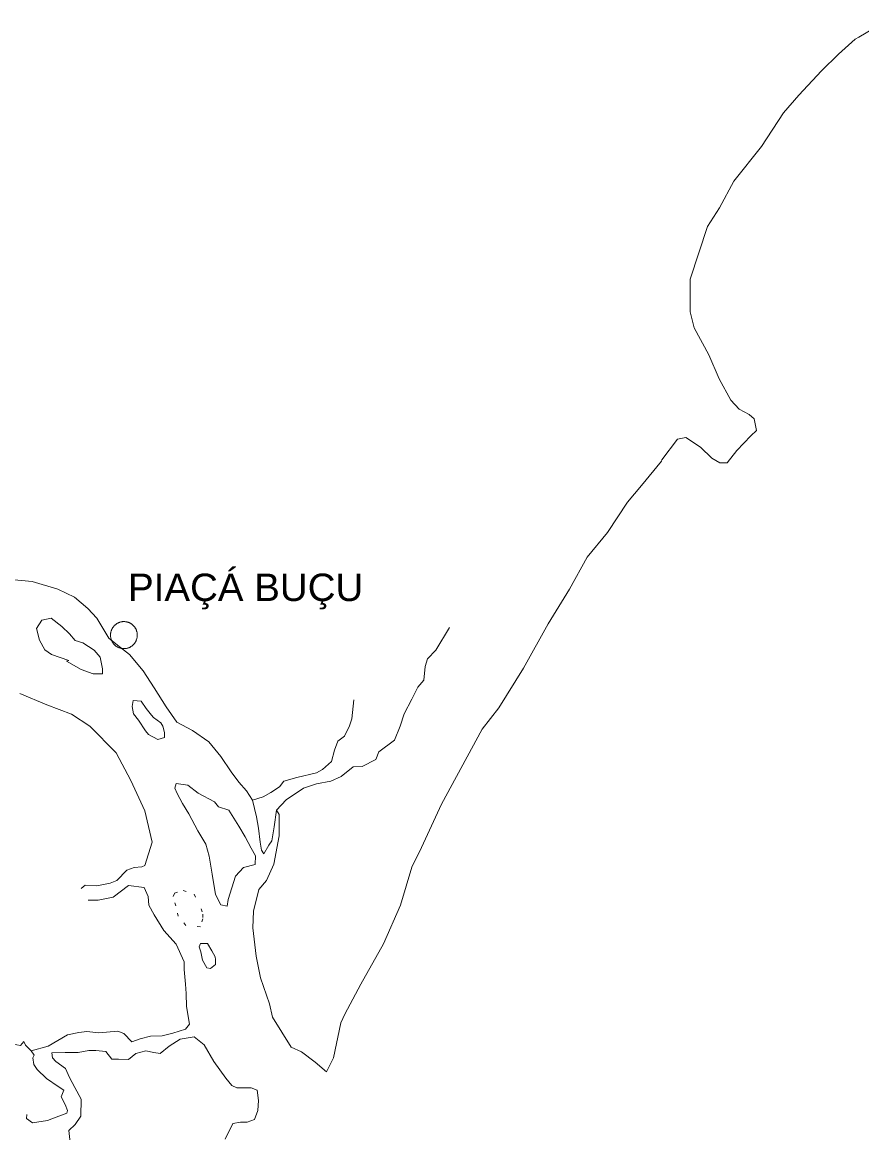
# Model space of a CAD drawing. Extents: x 47169 to 972804, y 7447977 to 9608469.
# Drawn here: x 778748 to 799346, y 8836489 to 8863725 of the extents above; entities that cross this region are included whole.
import ezdxf

# ---------------------------------------------------------------- set-up
doc = ezdxf.new("R2010")
doc.units = 0
doc.header["$LTSCALE"] = 270
doc.linetypes.add('DOTTED', pattern=[1.5, 0.3, -1.2])
doc.layers.add('1', color=7, linetype='Continuous', lineweight=13)
doc.layers.add('3', color=7, linetype='Continuous')

msp = doc.modelspace()

# ---------------------------------------------------------------- linework, layer by layer
at = {"layer": '1'}
for points in [[(799271.3, 8863361), (799891.1, 8863725.4)], [(795667.6, 8853035.2), (795864, 8852922.8), (796039.3, 8852921.3), (796282.9, 8853218.1), (796625.8, 8853580.5), (796758.4, 8853712.2), (796706.1, 8854000.4), (796586.4, 8854101.1), (796335.4, 8854236.1), (796129.1, 8854459.2), (795848.5, 8854981.8), (795590.5, 8855570.7), (795234.3, 8856226.8), (795139, 8856626.1), (795134.8, 8857423.1), (795562.2, 8858714.5), (795851.1, 8859177), (796207.4, 8859827.1), (796883.3, 8860673.7), (797427.4, 8861499.2), (797803.9, 8861938.8), (798357, 8862531.9), (798777.1, 8862937.9), (799185.9, 8863310.8), (799271.3, 8863361)], [(777496.4, 8850152.1), (778996.4, 8850007.2), (779619.6, 8849825.2), (780034.3, 8849622.6), (780360.8, 8849343.3), (780578, 8849109.1), (780869.9, 8848619.7), (781087.7, 8848451.9), (781381.7, 8848217.1), (781718.1, 8847816), (781988.6, 8847404.2), (782280.7, 8846937), (782540.5, 8846558.6), (782922.4, 8846356.2), (783325.5, 8846076.2), (783618.4, 8845719.7), (783878.2, 8845341.2), (784062.4, 8845085.1), (784246.9, 8844873.3), (784398.5, 8844650.7), (784493.7, 8844240.4), (784546.2, 8843963.3), (784587.2, 8843619.8), (784618.4, 8843420.3), (784672.5, 8843331.3), (784794.7, 8843540.6), (784872.3, 8843650.7), (784929.9, 8843993.3), (784988.1, 8844402.4), (785052.9, 8844291.1), (785048.6, 8843771), (784922.3, 8843074.7), (784743.8, 8842677.7), (784555.7, 8842457.9), (784419.9, 8841927.7), (784405.6, 8841518.3), (784487.5, 8840820.3), (784592.6, 8840288.2), (784817.4, 8839655.5), (784891.3, 8839322.8), (785345.4, 8838588.5), (785596.4, 8838475.8), (785933.8, 8838218.4), (786216.7, 8837983.6), (786383.8, 8838325.3), (786566.3, 8839187.1), (786666.6, 8839396.6), (787056.2, 8840134.9), (787612.2, 8841126.5), (788025.5, 8842074.9), (788307.1, 8843002.3), (788541.3, 8843487.4), (789032.2, 8844545.9), (790033.7, 8846386), (790443.5, 8846913.8), (791043.4, 8847882.9), (791655.2, 8848973.5), (792177.4, 8849821.4), (792611.3, 8850603.7), (793109.6, 8851208.3), (793598.1, 8851956.9), (793941.3, 8852363.5), (794428.5, 8852957.1), (794439.8, 8852990.2), (794827.6, 8853496.1), (795025.3, 8853538.7), (795384.9, 8853303.2), (795667.6, 8853035.2)], [(781571.8, 8848691.5), (781571.9, 8848702.6), (781570.9, 8848714.8), (781569.8, 8848725.8), (781568.8, 8848738), (781566.8, 8848749.1), (781564.7, 8848760.2), (781562.6, 8848772.4), (781559.4, 8848783.5), (781556.2, 8848794.6), (781553, 8848805.7), (781548.7, 8848815.7), (781544.4, 8848826.8), (781540.1, 8848837.9), (781534.7, 8848847.9), (781529.3, 8848857.9), (781522.8, 8848867.9), (781517.4, 8848877.9), (781510.9, 8848886.8), (781503.3, 8848896.8), (781496.8, 8848905.8), (781489.2, 8848914.7), (781481.6, 8848922.5), (781472.9, 8848931.4), (781465.3, 8848939.2), (781456.6, 8848947), (781447.9, 8848953.7), (781438.1, 8848961.6), (781429.4, 8848968.3), (781419.6, 8848973.9), (781409.8, 8848980.6), (781399.9, 8848986.2), (781390.1, 8848991.8), (781379.2, 8848996.3), (781368.3, 8849000.9), (781358.5, 8849005.4), (781347.5, 8849008.8), (781336.6, 8849012.2), (781325.7, 8849015.6), (781313.6, 8849017.9), (781302.7, 8849020.2), (781291.8, 8849022.5), (781279.7, 8849023.7), (781268.8, 8849024.9), (781256.7, 8849026.1), (781245.8, 8849026.2), (781234.8, 8849026.3), (781222.7, 8849025.3), (781211.8, 8849024.3), (781199.7, 8849023.3), (781188.7, 8849021.1), (781177.8, 8849019), (781165.7, 8849016.9), (781154.7, 8849013.7), (781143.7, 8849010.4), (781132.8, 8849007.2), (781122.8, 8849002.9), (781111.9, 8848998.5), (781100.9, 8848994.2), (781091, 8848988.7), (781081.1, 8848983.3), (781071.1, 8848976.7), (781061.2, 8848971.2), (781052.4, 8848964.7), (781042.5, 8848957), (781033.7, 8848950.4), (781024.8, 8848942.8), (781017.1, 8848935.1), (781008.3, 8848926.3), (781000.5, 8848918.6), (780992.8, 8848909.8), (780986.2, 8848901), (780978.4, 8848891.1), (780971.8, 8848882.3), (780966.2, 8848872.4), (780959.5, 8848862.5), (780954, 8848852.6), (780948.4, 8848842.7), (780944, 8848831.6), (780939.5, 8848820.6), (780935, 8848810.7), (780931.7, 8848799.6), (780928.3, 8848788.6), (780924.9, 8848777.6), (780922.6, 8848765.4), (780920.3, 8848754.3), (780918, 8848743.3), (780916.8, 8848731.1), (780915.7, 8848720.1), (780914.5, 8848707.9), (780914.4, 8848696.8), (780914.3, 8848685.8), (780915.3, 8848673.6), (780916.3, 8848662.5), (780917.3, 8848650.3), (780919.4, 8848639.3), (780921.5, 8848628.2), (780923.6, 8848616), (780926.8, 8848604.9), (780930, 8848593.8), (780933.2, 8848582.7)], [(784988.1, 8844402.4), (785220.2, 8844655), (785649.9, 8844939.2), (785968.5, 8845047.3), (786319.6, 8845110.8), (786572.6, 8845230.5), (786870.4, 8845460.4), (787089.6, 8845469.7), (787419.7, 8845644), (787498, 8845831.6), (787883.8, 8846116.1), (788018.2, 8846458.1), (788119.3, 8846767.2), (788308.6, 8847119.8), (788453.5, 8847417.5), (788597.4, 8847593.4), (788633, 8847925.1), (788689.4, 8848112.8), (788899.3, 8848321.4), (789232.7, 8848883.1)], [(780933.2, 8848582.7), (780937.5, 8848572.7), (780941.8, 8848561.6), (780946.1, 8848550.5), (780951.5, 8848540.5), (780956.8, 8848530.5), (780963.3, 8848520.5), (780968.8, 8848510.5), (780975.2, 8848501.6), (780982.8, 8848491.5), (780989.3, 8848482.6), (780996.9, 8848473.7), (781004.6, 8848465.9), (781013.2, 8848457), (781020.8, 8848449.2), (781029.6, 8848441.4), (781038.3, 8848434.6), (781048.1, 8848426.8), (781056.8, 8848420.1), (781066.6, 8848414.5), (781076.4, 8848407.8), (781086.2, 8848402.2), (781096, 8848396.5), (781107, 8848392), (781117.9, 8848387.5), (781127.7, 8848383), (781138.6, 8848379.6), (781149.6, 8848376.2), (781160.5, 8848372.8), (781172.5, 8848370.5), (781183.5, 8848368.2), (781194.4, 8848365.9), (781206.4, 8848364.7), (781217.4, 8848363.5), (781229.4, 8848362.3), (781240.4, 8848362.2), (781251.3, 8848362.1), (781263.4, 8848363.1), (781274.4, 8848364.1), (781286.4, 8848365.1), (781297.4, 8848367.2), (781308.4, 8848369.4), (781320.5, 8848371.5), (781331.4, 8848374.7), (781342.4, 8848377.9), (781353.4, 8848381.2), (781363.3, 8848385.5), (781374.3, 8848389.9), (781385.3, 8848394.2), (781395.2, 8848399.7), (781405.1, 8848405.1), (781415, 8848411.7), (781424.9, 8848417.1), (781433.7, 8848423.7), (781443.7, 8848431.3), (781452.5, 8848437.9), (781461.3, 8848445.6), (781469, 8848453.3), (781477.9, 8848462.1), (781485.6, 8848469.8), (781493.3, 8848478.5), (781500, 8848487.3), (781507.7, 8848497.2), (781514.4, 8848506.1), (781519.9, 8848516), (781526.6, 8848525.9), (781532.2, 8848535.8), (781537.7, 8848545.7), (781542.2, 8848556.7), (781546.7, 8848567.8), (781551.1, 8848577.7), (781554.5, 8848588.7), (781557.9, 8848599.8), (781561.2, 8848610.8), (781563.5, 8848623), (781565.8, 8848634), (781568.1, 8848645.1), (781569.3, 8848657.2), (781570.5, 8848668.3), (781571.7, 8848680.5), (781571.8, 8848691.5)], [(780195.7, 8842482.5), (780294.9, 8842559.2), (780579.6, 8842545.8), (780908.8, 8842609.5), (781073.7, 8842674.6), (781316.7, 8842927.2), (781492.6, 8842992.1), (781679, 8843012.8), (781755.9, 8843045.3), (781935.9, 8843619.4), (781755.9, 8844384.6), (781411.3, 8845128.9), (781055.3, 8845807), (780403.3, 8846465.3), (779956.4, 8846756.6), (779355.6, 8846982.8), (778689.5, 8847264.9)], [(784398.5, 8844650.7), (784662.1, 8844726), (784849.2, 8844835.2), (785058.6, 8844977.3), (785169.2, 8845109.2), (785487.7, 8845206.2), (785970.7, 8845312.9), (786113.9, 8845400.3), (786334.6, 8845597.7), (786413.6, 8845873.7), (786492.1, 8846094.5), (786657.5, 8846214.8), (786780.1, 8846468.4), (786836.3, 8846645), (786884, 8847109.5)], [(778969.3, 8838496.9), (779386.5, 8838615.3), (779859.8, 8838888.1), (780134.1, 8838952.3), (780331.5, 8838972.8), (780626.9, 8838937.2), (781098.3, 8838977.7), (781240.2, 8838921.2), (781435.8, 8838720.3), (781644.5, 8838796.1), (781897, 8838860.4), (782181.9, 8838869.2), (782445.3, 8838933.4), (782752.8, 8839030.5), (782852.4, 8839151.4), (782779.3, 8839583.7), (782771, 8839904.8), (782751, 8840137.3), (782721, 8840491.8), (782722.6, 8840679.9), (782528.9, 8841113.2), (782224.9, 8841447.7), (781987.1, 8841837), (781857.5, 8842070.5), (781837.3, 8842281), (781740.6, 8842503.1), (781357.5, 8842550.5), (780982.7, 8842265.8), (780609.6, 8842191.4), (780368.6, 8842193.3)], [(776679.2, 8838404.8), (776942.1, 8838402.6), (777270.7, 8838400), (777644.6, 8838585.1), (777995.6, 8838648.7), (778237.7, 8838779.6), (778359.6, 8838955.7), (778434, 8838678.3), (778707.5, 8838631.9), (778785, 8838730.8), (778828.1, 8838641.9), (778969.3, 8838496.9)], [(779925.9, 8836253.4), (779895.4, 8836541.4), (780050, 8836695.1), (780183.1, 8836893.3), (780197.5, 8837313.7), (780035.5, 8837602.8), (779906.1, 8837847.4), (779809.3, 8838069.5), (779569.7, 8838237.5), (779493.7, 8838326.7), (779472.8, 8838448.6), (779801.5, 8838457), (780119.1, 8838454.4), (780382.4, 8838507.6), (780557.7, 8838506.1), (780798.5, 8838482.1), (780950.3, 8838292.7), (781114.6, 8838291.3), (781355.6, 8838289.3), (781532, 8838431.8), (781784.5, 8838496.1), (781981.4, 8838461.3), (782134.5, 8838437.9), (782355, 8838613.2), (782619.4, 8838788.1), (782970.3, 8838840.6), (783209.8, 8838650.4), (783447.4, 8838239), (783739.7, 8837827), (783891.6, 8837648.7), (784011.7, 8837592.3), (784362.2, 8837589.4), (784515, 8837532.8), (784545.8, 8837278), (784532.8, 8837034.6), (784443.4, 8836814), (784267.6, 8836749), (784103.3, 8836750.4), (783916.8, 8836718.7), (783727.4, 8836332.9)], [(778969.3, 8838496.9), (779045.2, 8838396.7), (779011.8, 8838330.6), (779032.3, 8838164.4), (779119, 8838041.9), (779347.2, 8837818.7), (779630.4, 8837628.3), (779772.1, 8837538.6), (779705, 8837373.1), (779802.1, 8837184.2), (779855.7, 8837039.8), (779844.2, 8836973.5), (779580.5, 8836876.1), (779371.7, 8836789.2), (778998.8, 8836736.9), (778857.3, 8836837.7), (778858.1, 8836937.3)]]:
    msp.add_lwpolyline(points, dxfattribs=at)
for points in [[(779890.3, 8848074.2), (779464.2, 8848221.6), (779300.8, 8848333.6), (779171.1, 8848567), (779096.8, 8848855.4), (779229.9, 8849064.6), (779460.4, 8849107), (779721.7, 8848905.7), (779906.6, 8848727.1), (780047.7, 8848560), (780233.5, 8848503.1), (780516.9, 8848323.8), (780658, 8848156.6), (780679.2, 8848067.9), (780721.4, 8847868.3), (780720.4, 8847746.6), (780490.3, 8847748.4), (780195.3, 8847850.4), (779835.4, 8848052.6)], [(781598.7, 8846610.5), (781479.4, 8846766.4), (781448, 8846943.8), (781471.1, 8847087.5), (781668.2, 8847074.8), (781787.3, 8846896.8), (781917.4, 8846729.7), (781971.7, 8846673.9), (782146, 8846539.7), (782200.1, 8846461.7), (782242.7, 8846306.4), (782241.7, 8846184.7), (782076.9, 8846130.7), (781847.8, 8846254.3), (781771.8, 8846343.5)], [(783055.7, 8843898), (782839.9, 8844309.3), (782677.7, 8844565.2), (782548.2, 8844809.8), (782494.5, 8844943), (782528.3, 8845053.4), (782812.8, 8845017.9), (783063.2, 8844816.6), (783466.8, 8844603), (783564.4, 8844480.5), (783815.8, 8844400.9), (784064.6, 8844011.5), (784215.7, 8843744.6), (784366.8, 8843466.7), (784474.8, 8843277.6), (784462.2, 8843067.4), (784176.7, 8842992.3), (783977.8, 8842783.6), (783797.8, 8842209.6), (783774.5, 8842043.7), (783621.4, 8842078.2), (783492, 8842333.8), (783408.5, 8842832.6), (783335.4, 8843275.9), (783250.1, 8843564.4)], [(783129.9, 8840931.1), (783087.1, 8841053.2), (783120.6, 8841130.4), (783295.9, 8841129), (783404, 8840951), (783479.5, 8840806.5), (783489.9, 8840740), (783488.9, 8840618.3), (783367.6, 8840519.7), (783280, 8840531.5), (783172, 8840720.5)]]:
    msp.add_lwpolyline(points, close=True, dxfattribs=at)
at = {"layer": '1', "linetype": 'DOTTED'}
msp.add_lwpolyline([(783138.6, 8841982.6), (783181.3, 8841849.4), (783180.4, 8841738.7), (783124, 8841539.9), (782762.8, 8841576.1), (782578.3, 8841799), (782514.7, 8842054.1), (782450.9, 8842287), (782484.4, 8842364.2), (782693.1, 8842428.9), (782966.2, 8842338.1)], close=True, dxfattribs=at)

# ---------------------------------------------------------------- texts
at = {"layer": '3', "width": 1.05}
msp.add_text('PIAÇÁ BUÇU', height=672.6, dxfattribs=at).set_placement((781343.9, 8849530))

doc.saveas('drawing.dxf')
